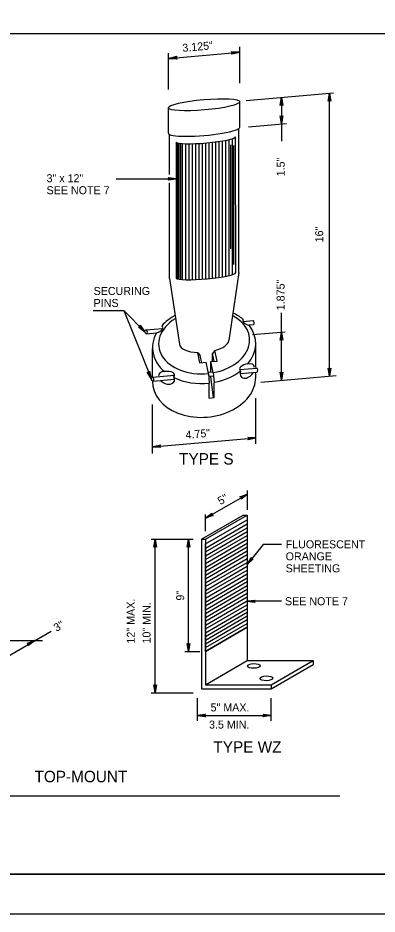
# Model space of a CAD drawing. Extents: x 640253 to 641999, y 298458 to 299646.
# Drawn here: x 640662 to 640796.8, y 298457.6 to 298793.5 of the extents above; entities that cross this region are included whole.
import ezdxf

# ---------------------------------------------------------------- set-up
doc = ezdxf.new("R2010")
doc.units = 0
for name, color, linetype in [('1', 7, 'Continuous'), ('2', 7, 'Continuous'), ('PLT-BNDY', 7, 'Continuous')]:
    doc.layers.add(name, color=color, linetype=linetype)

msp = doc.modelspace()

# ---------------------------------------------------------------- linework, layer by layer
at = {"layer": '1'}
for p, q in [((640293.31, 298787.67), (641079.31, 298787.67)), ((640318.26, 298501.97), (640782.88, 298501.97)), ((641079.31, 298472.63), (640293.31, 298472.63)), ((640293.31, 298472.63), (640879.31, 298472.63))]:
    msp.add_line(p, q, dxfattribs=at)
at = {"layer": '2'}
for p, q in [((640718.51, 298778.37), (640745.35, 298780.72)), ((640718.51, 298766.76), (640718.51, 298780.28)), ((640745.35, 298769.11), (640745.35, 298782.64)), ((640747.71, 298762.61), (640780.48, 298765.48)), ((640760.93, 298763.77), (640760.93, 298753.8)), ((640778.98, 298659.27), (640778.98, 298765.33)), ((640745.35, 298752.61), (640745.35, 298762.15)), ((640718.51, 298750.3), (640718.51, 298759.84)), ((640748.58, 298752.71), (640762.8, 298753.96)), ((640760.93, 298753.8), (640760.93, 298747.37)), ((640744.97, 298698.11), (640744.96, 298752.08)), ((640718.9, 298734.89), (640718.9, 298749.84)), ((640721.41, 298746.98), (640721.41, 298696)), ((640721.41, 298746.59), (640721.63, 298746.81)), ((640732.61, 298695.69), (640732.61, 298746.66)), ((640733.86, 298695.81), (640733.86, 298746.78)), ((640735.11, 298695.94), (640735.11, 298746.91)), ((640736.36, 298696.1), (640736.36, 298747.07)), ((640737.61, 298696.27), (640737.61, 298747.24)), ((640738.86, 298696.47), (640738.86, 298747.44)), ((640740.11, 298696.7), (640740.11, 298747.67)), ((640741.36, 298696.98), (640741.36, 298747.95)), ((640742.61, 298697.33), (640742.61, 298748.3)), ((640743.76, 298748.51), (640743.55, 298748.73)), ((640743.77, 298698.07), (640743.76, 298748.98)), ((640722.06, 298695.59), (640722.06, 298746.56)), ((640722.61, 298695.59), (640722.61, 298746.55)), ((640723.24, 298695.59), (640723.24, 298746.56)), ((640723.86, 298695.45), (640723.86, 298746.43)), ((640725.11, 298695.4), (640725.11, 298746.37)), ((640726.36, 298695.39), (640726.36, 298746.36)), ((640727.61, 298695.4), (640727.61, 298746.38)), ((640728.86, 298695.45), (640728.86, 298746.42)), ((640730.11, 298695.51), (640730.11, 298746.48)), ((640731.36, 298695.59), (640731.36, 298746.57)), ((640741.93, 298706.99), (640741.93, 298745.92)), ((640743.12, 298701.13), (640743.12, 298745.69)), ((640698.95, 298733.24), (640721.41, 298733.24)), ((640718.91, 298695.83), (640718.9, 298731.67)), ((640744.97, 298698.11), (640741.18, 298672.58)), ((640718.91, 298695.83), (640722.69, 298671.24)), ((640690.3, 298683.85), (640701.76, 298683.85)), ((640701.76, 298683.85), (640709.73, 298675.91)), ((640701.76, 298683.85), (640712.18, 298658.13)), ((640760.93, 298657.71), (640760.93, 298682.93)), ((640746.61, 298679.77), (640750.3, 298680.09)), ((640710.07, 298676.65), (640716.25, 298677.17)), ((640748.75, 298678.44), (640750.42, 298678.58)), ((640710.18, 298675.14), (640714.07, 298675.47)), ((640750.09, 298674.81), (640762.33, 298675.88)), ((640712.57, 298658.9), (640712.57, 298669.6)), ((640751.32, 298662.52), (640751.32, 298671.49)), ((640730.36, 298664.26), (640729.56, 298668.13)), ((640729.58, 298668.02), (640730.45, 298667.02)), ((640731.01, 298664.3), (640730.45, 298667.02)), ((640736.01, 298668.88), (640735.1, 298667.79)), ((640735.1, 298664.75), (640735.1, 298667.79)), ((640735.72, 298664.82), (640735.1, 298667.79)), ((640736.83, 298664.91), (640736, 298668.9)), ((640730.36, 298664.26), (640732.68, 298664.47)), ((640733.56, 298660.25), (640732.68, 298664.47)), ((640734.51, 298664.7), (640736.83, 298664.91)), ((640735.37, 298660.56), (640734.51, 298664.7)), ((640734.51, 298660.92), (640734.51, 298664.7)), ((640712.51, 298658.91), (640720.85, 298659.63)), ((640733.46, 298660.71), (640735.31, 298660.86)), ((640733.56, 298660.25), (640733.88, 298656.62)), ((640733.65, 298659.21), (640735.48, 298659.36)), ((640735.37, 298660.56), (640735.7, 298656.93)), ((640745.28, 298661.72), (640751.64, 298662.26)), ((640745.44, 298660.21), (640751.77, 298660.75)), ((640751.32, 298658.55), (640751.32, 298660.75)), ((640753.15, 298657.03), (640781.49, 298659.51)), ((640712.63, 298657.41), (640720.84, 298658.11)), ((640733.88, 298651.05), (640733.88, 298656.62)), ((640735.5, 298651.22), (640734.51, 298659.03)), ((640735.7, 298651.21), (640735.7, 298656.93)), ((640733.88, 298651.05), (640735.7, 298651.21)), ((640751.32, 298633.93), (640751.32, 298651.02)), ((640712.57, 298630.28), (640712.57, 298648.65)), ((640712.57, 298632.73), (640751.32, 298636.12)), ((640748.2, 298609.2), (640748.2, 298616.39)), ((640732.46, 298605.99), (640748.2, 298615.08)), ((640730.89, 298598.1), (640746.63, 298607.19)), ((640732.39, 298598.1), (640748.13, 298607.19)), ((640732.46, 298601.21), (640732.46, 298607.46)), ((640746.63, 298607.19), (640748.13, 298607.19)), ((640748.13, 298607.19), (640748.13, 298552.69)), ((640732.39, 298594.81), (640748.13, 298603.9)), ((640732.39, 298593.37), (640748.13, 298602.46)), ((640732.39, 298591.92), (640748.13, 298601.01)), ((640732.39, 298590.48), (640748.13, 298599.57)), ((640712.01, 298598.1), (640727.76, 298598.1)), ((640713.55, 298540.6), (640713.55, 298598.1)), ((640726.09, 298556.11), (640726.09, 298598.1)), ((640730.89, 298598.1), (640732.39, 298598.1)), ((640730.89, 298598.1), (640730.89, 298542.1)), ((640732.39, 298589.04), (640748.13, 298598.13)), ((640732.39, 298598.1), (640732.39, 298543.6)), ((640732.39, 298587.59), (640748.13, 298596.68)), ((640732.39, 298596.1), (640732.61, 298596.5)), ((640732.39, 298596.14), (640732.58, 298596.48)), ((640754.14, 298596.12), (640748.13, 298588.7)), ((640760.91, 298596.12), (640754.14, 298596.12)), ((640732.39, 298586.15), (640748.13, 298595.24)), ((640732.39, 298584.71), (640748.13, 298593.8)), ((640732.39, 298583.26), (640748.13, 298592.35)), ((640732.39, 298581.82), (640748.13, 298590.91)), ((640732.39, 298580.38), (640748.13, 298589.47)), ((640732.39, 298578.93), (640748.13, 298588.02)), ((640732.39, 298577.49), (640748.13, 298586.58)), ((640732.39, 298576.05), (640748.13, 298585.14)), ((640732.39, 298574.6), (640748.13, 298583.69)), ((640732.39, 298573.16), (640748.13, 298582.25)), ((640732.39, 298571.72), (640748.13, 298580.81)), ((640732.39, 298570.27), (640748.13, 298579.36)), ((640732.39, 298568.83), (640748.13, 298577.92)), ((640732.39, 298567.39), (640748.13, 298576.48)), ((640732.39, 298565.94), (640748.13, 298575.03)), ((640732.39, 298564.5), (640748.13, 298573.59)), ((640732.39, 298563.1), (640748.13, 298572.19)), ((640760.91, 298574.86), (640748.13, 298574.86)), ((640732.39, 298561.71), (640748.13, 298570.79)), ((640732.39, 298560.31), (640748.13, 298569.4)), ((640732.39, 298558.91), (640748.13, 298568)), ((640732.39, 298557.51), (640748.13, 298566.6)), ((640652.59, 298551.06), (640674.47, 298563.69)), ((640732.39, 298556.11), (640748.13, 298565.2)), ((640654.65, 298560.16), (640671.23, 298560.16)), ((640724.73, 298556.11), (640730.31, 298556.11)), ((640732.39, 298543.6), (640748.13, 298552.69)), ((640748.13, 298552.69), (640772.85, 298552.69)), ((640757.1, 298543.6), (640772.85, 298552.69)), ((640772.85, 298552.69), (640772.85, 298551.2)), ((640757.1, 298542.1), (640772.85, 298551.2)), ((640730.89, 298542.1), (640757.1, 298542.1)), ((640732.39, 298543.6), (640757.1, 298543.6)), ((640757.1, 298543.6), (640757.1, 298542.1)), ((640712.01, 298540.6), (640727.76, 298540.6)), ((640729.39, 298530.05), (640729.39, 298538.56)), ((640757.1, 298530.05), (640757.1, 298538.56)), ((640729.39, 298532.09), (640757.1, 298532.09))]:
    msp.add_line(p, q, dxfattribs=at)
for points in [[(640742.24, 298780.84), (640742.38, 298780.63), (640745.35, 298780.72), (640742.24, 298780.84), (640742.07, 298780.96), (640745.35, 298780.72), (640742.41, 298780.32), (640742.32, 298780.09), (640745.35, 298780.72), (640742.17, 298779.92), (640742.32, 298780.09)], [(640721.62, 298778.25), (640721.48, 298778.47), (640718.51, 298778.37), (640721.62, 298778.25), (640721.78, 298778.13), (640718.51, 298778.37), (640721.45, 298778.78), (640721.54, 298779.01), (640718.51, 298778.37), (640721.69, 298779.17), (640721.54, 298779.01)], [(640721.62, 298778.25), (640721.48, 298778.47), (640718.51, 298778.37), (640721.62, 298778.25), (640721.78, 298778.13), (640718.51, 298778.37), (640721.45, 298778.78), (640721.54, 298779.01), (640718.51, 298778.37), (640721.69, 298779.17), (640721.54, 298779.01)], [(640760.57, 298760.91), (640760.78, 298761.02), (640760.93, 298763.77), (640760.57, 298760.91), (640760.45, 298760.77), (640760.93, 298763.77), (640761.06, 298761.02), (640761.27, 298760.92), (640760.93, 298763.77), (640761.41, 298760.77), (640761.27, 298760.92)], [(640778.62, 298762.47), (640778.83, 298762.58), (640778.98, 298765.33), (640778.62, 298762.47), (640778.5, 298762.33), (640778.98, 298765.33), (640779.12, 298762.58), (640779.32, 298762.48), (640778.98, 298765.33), (640779.46, 298762.33), (640779.32, 298762.48)], [(640761.29, 298756.65), (640761.08, 298756.54), (640760.93, 298753.8), (640761.29, 298756.65), (640761.41, 298756.8), (640760.93, 298753.8), (640760.79, 298756.54), (640760.59, 298756.64), (640760.93, 298753.8), (640760.45, 298756.8), (640760.59, 298756.64)], [(640718.56, 298733.6), (640718.66, 298733.39), (640721.41, 298733.24), (640718.56, 298733.6), (640718.41, 298733.72), (640721.41, 298733.24), (640718.66, 298733.11), (640718.56, 298732.9), (640721.41, 298733.24), (640718.41, 298732.76), (640718.56, 298732.9)], [(640707.95, 298678.17), (640707.88, 298677.95), (640709.73, 298675.91), (640707.95, 298678.17), (640707.93, 298678.36), (640709.73, 298675.91), (640707.68, 298677.74), (640707.47, 298677.67), (640709.73, 298675.91), (640707.26, 298677.68), (640707.47, 298677.67)], [(640760.57, 298672.9), (640760.78, 298673.01), (640760.93, 298675.75), (640760.57, 298672.9), (640760.45, 298672.75), (640760.93, 298675.75), (640761.06, 298673.01), (640761.27, 298672.91), (640760.93, 298675.75), (640761.41, 298672.75), (640761.27, 298672.91)], [(640711.42, 298660.91), (640711.27, 298660.73), (640712.18, 298658.13), (640711.42, 298660.91), (640711.48, 298661.09), (640712.18, 298658.13), (640711.01, 298660.62), (640710.78, 298660.64), (640712.18, 298658.13), (640710.59, 298660.73), (640710.78, 298660.64)], [(640761.29, 298660.57), (640761.08, 298660.46), (640760.93, 298657.71), (640761.29, 298660.57), (640761.41, 298660.71), (640760.93, 298657.71), (640760.79, 298660.46), (640760.59, 298660.56), (640760.93, 298657.71), (640760.45, 298660.71), (640760.59, 298660.56)], [(640779.34, 298662.13), (640779.13, 298662.02), (640778.98, 298659.27), (640779.34, 298662.13), (640779.46, 298662.27), (640778.98, 298659.27), (640778.85, 298662.02), (640778.64, 298662.12), (640778.98, 298659.27), (640778.5, 298662.27), (640778.64, 298662.12)], [(640748.44, 298636.23), (640748.57, 298636.03), (640751.32, 298636.12), (640748.44, 298636.23), (640748.29, 298636.34), (640751.32, 298636.12), (640748.6, 298635.75), (640748.51, 298635.53), (640751.32, 298636.12), (640748.37, 298635.38), (640748.51, 298635.53)], [(640715.45, 298632.62), (640715.32, 298632.82), (640712.57, 298632.73), (640715.45, 298632.62), (640715.6, 298632.51), (640712.57, 298632.73), (640715.29, 298633.1), (640715.37, 298633.32), (640712.57, 298632.73), (640715.52, 298633.47), (640715.37, 298633.32)], [(640745.55, 298613.97), (640745.75, 298613.84), (640748.2, 298615.08), (640745.55, 298613.97), (640745.36, 298614), (640748.2, 298615.08), (640745.89, 298613.59), (640745.91, 298613.37), (640748.2, 298615.08), (640745.84, 298613.17), (640745.91, 298613.37)], [(640735.11, 298607.11), (640734.91, 298607.24), (640732.46, 298605.99), (640735.11, 298607.11), (640735.3, 298607.08), (640732.46, 298605.99), (640734.77, 298607.48), (640734.75, 298607.71), (640732.46, 298605.99), (640734.82, 298607.91), (640734.75, 298607.71)], [(640713.19, 298595.25), (640713.4, 298595.36), (640713.55, 298598.1), (640713.19, 298595.25), (640713.06, 298595.1), (640713.55, 298598.1), (640713.68, 298595.36), (640713.89, 298595.26), (640713.55, 298598.1), (640714.02, 298595.1), (640713.89, 298595.26)], [(640725.73, 298595.25), (640725.94, 298595.36), (640726.09, 298598.1), (640725.73, 298595.25), (640725.61, 298595.1), (640726.09, 298598.1), (640726.22, 298595.36), (640726.43, 298595.26), (640726.09, 298598.1), (640726.57, 298595.1), (640726.43, 298595.26)], [(640750.2, 298590.69), (640749.97, 298590.74), (640748.13, 298588.7), (640750.2, 298590.69), (640750.39, 298590.73), (640748.13, 298588.7), (640749.75, 298590.92), (640749.65, 298591.13), (640748.13, 298588.7), (640749.64, 298591.33), (640749.65, 298591.13)], [(640750.98, 298574.51), (640750.87, 298574.71), (640748.13, 298574.86), (640750.98, 298574.51), (640751.13, 298574.38), (640748.13, 298574.86), (640750.87, 298575), (640750.97, 298575.2), (640748.13, 298574.86), (640751.13, 298575.34), (640750.97, 298575.2)], [(640665.7, 298559.04), (640665.89, 298558.92), (640668.35, 298560.16), (640665.7, 298559.04), (640665.51, 298559.08), (640668.35, 298560.16), (640666.04, 298558.67), (640666.05, 298558.44), (640668.35, 298560.16), (640665.99, 298558.24), (640666.05, 298558.44)], [(640726.45, 298558.97), (640726.24, 298558.86), (640726.09, 298556.11), (640726.45, 298558.97), (640726.57, 298559.11), (640726.09, 298556.11), (640725.95, 298558.86), (640725.75, 298558.96), (640726.09, 298556.11), (640725.61, 298559.11), (640725.75, 298558.96)], [(640713.91, 298543.46), (640713.7, 298543.35), (640713.55, 298540.6), (640713.91, 298543.46), (640714.03, 298543.6), (640713.55, 298540.6), (640713.41, 298543.35), (640713.21, 298543.45), (640713.55, 298540.6), (640713.07, 298543.6), (640713.21, 298543.45)], [(640732.24, 298531.74), (640732.14, 298531.94), (640729.39, 298532.09), (640732.24, 298531.74), (640732.39, 298531.61), (640729.39, 298532.09), (640732.13, 298532.23), (640732.23, 298532.43), (640729.39, 298532.09), (640732.39, 298532.57), (640732.23, 298532.43)], [(640754.25, 298532.45), (640754.36, 298532.25), (640757.1, 298532.09), (640754.25, 298532.45), (640754.1, 298532.58), (640757.1, 298532.09), (640754.36, 298531.96), (640754.26, 298531.76), (640757.1, 298532.09), (640754.1, 298531.62), (640754.26, 298531.76)]]:
    msp.add_lwpolyline(points, dxfattribs=at)
msp.add_lwpolyline([(640732.39, 298556.11), (640732.39, 298596.37), (640748.13, 298605.46), (640748.13, 298565.2)], close=True, dxfattribs=at)
for centre, major_axis, ratio in [((640731.93, 298760.98), (13.42, 1.17), 0.145281), ((640710.12, 298675.89), (0.064, -0.752), 0.512732), ((640712.57, 298658.16), (0.064, -0.752), 0.512732), ((640750.54, 298550.64), (2.36, 0.05), 0.379302), ((640755.3, 298545.98), (2.36, 0.05), 0.379302)]:
    msp.add_ellipse(centre, major_axis=major_axis, ratio=ratio, dxfattribs=at)
for centre, major_axis, ratio, start_param, end_param in [((640731.93, 298751.43), (13.42, 1.17), 0.145281, 3.11632, 6.285895), ((640732.57, 298748.05), (11.2, 0.98), 0.122972, 3.210002, 6.25293), ((640732.58, 298697.08), (11.2, 0.98), 0.122972, 3.210002, 6.291685), ((640731.94, 298670.7), (19.33, 1.69), 0.73071, 0.656059, 0.918196), ((640731.94, 298672.08), (17.07, 1.49), 0.694967, 2.202733, 4.738504), ((640731.94, 298670.7), (19.33, 1.69), 0.73071, 2.097917, 2.468804), ((640731.94, 298672.08), (17.07, 1.49), 0.694967, 4.864246, 7.131508), ((640750.78, 298680.04), (4.38, -0.28), 0.475219, 2.977963, 4.296796), ((640750.36, 298679.33), (0.064, -0.752), 0.512732, 0.00107, 3.141593), ((640712.01, 298677.2), (-4.38, -0.28), 0.475219, 2.036448, 3.493745), ((640731.94, 298670.7), (19.33, 1.69), 0.73071, 5.661526, 6.723992), ((640731.94, 298670.7), (19.33, 1.69), 0.73071, 2.680187, 3.772289), ((640731.73, 298672.03), (9.04, 0.79), 0.424128, 3.141593, 4.432781), ((640732.14, 298672.12), (9.04, 0.79), 0.424128, 5.116194, 6.19738), ((640748.9, 298662.15), (3.65, 0.24), 0.475219, 1.675831, 3.574843), ((640748.15, 298661.2), (2.24, 2.27), 0.672987, 5.779184, 7.175378), ((640717.83, 298658.61), (2.87, -1.38), 0.672987, 2.130551, 3.418187), ((640717.22, 298659.25), (-3.62, -0.53), 0.475219, 2.692089, 4.679207), ((640731.94, 298670.7), (19.33, 1.69), 0.73071, 4.853626, 5.433989), ((640748.15, 298661.2), (2.24, 2.27), 0.672987, 2.176573, 5.044432), ((640751.7, 298661.51), (0.064, -0.752), 0.512732, 0.00107, 3.141593), ((640731.94, 298658.04), (19.33, 1.69), 0.73071, 3.065603, 6.219513), ((640717.83, 298658.61), (2.87, -1.38), 0.672987, 4.245803, 7.059428), ((640731.94, 298670.7), (19.33, 1.69), 0.73071, 4.023734, 4.749104)]:
    msp.add_ellipse(centre, major_axis=major_axis, ratio=ratio, start_param=start_param, end_param=end_param, dxfattribs=at)
at = {"layer": 'PLT-BNDY'}
msp.add_lwpolyline([(640253.31, 299051.63), (641094.31, 299051.63), (641094.31, 298457.63), (640253.31, 298457.63)], close=True, dxfattribs=at)

# ---------------------------------------------------------------- texts
at = {"layer": '2'}
for s, rotation, p in [('3.125"', 5.0068, (640723.91, 298780.79)), ('1.5"', 90, (640762.17, 298734.13)), ('16"', 90, (640776.61, 298709.41)), ('1.875"', 90, (640762.12, 298683.95)), ('4.75"', 5.0052, (640725.08, 298635.72)), ('5"', 30, (640738.05, 298610.87)), ('12" MAX.', 90, (640705.92, 298559.03)), ('9"', 90, (640724.44, 298575.13)), ('10" MIN.', 90, (640711.82, 298559.05)), ('3"', 30, (640676.53, 298563.35))]:
    msp.add_text(s, height=3, rotation=rotation, dxfattribs=at).set_placement(p)
for s, height, p in [('3" x 12"', 3, (640672.81, 298731.95)), ('SEE NOTE 7', 3, (640672.81, 298727.45)), ('SECURING', 3, (640690.46, 298689.69)), ('PINS', 3, (640690.46, 298685.19)), ('TYPE S', 4.3, (640722.54, 298626.11)), ('FLUORESCENT', 3, (640762.52, 298594.73)), ('ORANGE', 3, (640762.52, 298590.23)), ('SHEETING', 3, (640762.52, 298585.73)), ('SEE NOTE 7', 3, (640762.27, 298573.39)), ('5" MAX.', 3, (640734.36, 298533.59)), ('3.5 MIN.', 3, (640733.77, 298527.15)), ('TYPE WZ', 4.3, (640735.42, 298518.11)), ('TOP-MOUNT', 4.3, (640668.29, 298507.04))]:
    msp.add_text(s, height=height, dxfattribs=at).set_placement(p)

doc.saveas('drawing.dxf')
